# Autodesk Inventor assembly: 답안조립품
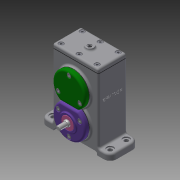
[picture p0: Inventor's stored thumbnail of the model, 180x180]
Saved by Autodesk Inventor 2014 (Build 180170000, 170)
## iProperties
Created: 2020-05
Part Number: 답안조립품
Document SubType Name: Assembly
Designer: kh
Mass: 1076.75 g
Surface Area: 1575.48 cm^2
Volume: 384.079 cm^3
Density: 2.80345 g/cm^3
Author: kh
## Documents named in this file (24)
- C:\Users\kh\Desktop\600506V1028\답안조립품.iam
- C:\Users\kh\Desktop\600506V1028\본체.ipt
- C:\Users\kh\Desktop\600506V1028\개스킷 A.ipt
- C:\Users\kh\Desktop\600506V1028\개스킷 B.ipt
- C:\Users\kh\Desktop\600506V1028\개스킷 C.ipt
- C:\Users\kh\Desktop\600506V1028\베어링 6001.ipt
- 베어링 6001.ipt
- C:\Users\kh\Desktop\600506V1028\베어링 6002.ipt
- 베어링 6002.ipt
- C:\Users\kh\Desktop\600506V1028\볼트 M4.ipt
- C:\Users\kh\Desktop\600506V1028\스퍼기어 A.ipt
- C:\Users\kh\Desktop\600506V1028\스퍼기어 B.ipt
- C:\Users\kh\Desktop\600506V1028\오일 실 10 20 7.ipt
- C:\Users\kh\Desktop\600506V1028\오일 실 12 22 7.ipt
- C:\Users\kh\Desktop\600506V1028\축 A.ipt
- C:\Users\kh\Desktop\600506V1028\축 B.ipt
- C:\Users\kh\Desktop\600506V1028\칼라.ipt
- C:\Users\kh\Desktop\600506V1028\커버 A.ipt
- C:\Users\kh\Desktop\600506V1028\커버 B.ipt
- C:\Users\kh\Desktop\600506V1028\커버 C.ipt
- C:\Users\kh\Desktop\600506V1028\커버 D.ipt
- C:\Users\kh\Desktop\600506V1028\커버 E.ipt
- C:\Users\kh\Desktop\600506V1028\키 4 x 4 x 12.ipt
- C:\Users\kh\Desktop\600506V1028\키 5 x 5 x 12.ipt
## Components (5 placed, 3 different names)
1. 개스킷 A:1
2. 개스킷 B:1
3. 개스킷 C:1
4. 개스킷 B:2
5. 개스킷 B:3
